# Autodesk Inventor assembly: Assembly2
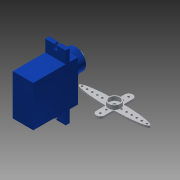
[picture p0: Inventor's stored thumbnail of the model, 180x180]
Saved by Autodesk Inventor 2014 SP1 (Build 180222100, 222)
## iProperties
Created: 2017-05
Part Number: Assembly2
Document SubType Name: Assembly
Designer: L.Đ.P
Author: L.Đ.P
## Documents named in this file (3)
- D:\Micro Servo 9g\Assembly2.iam
- D:\Micro Servo 9g\Micro Servo 9g.ipt
- D:\Micro Servo 9g\Part2.ipt
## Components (2 placed, 2 different names)
1. Micro Servo 9g:1
2. Part2:1
